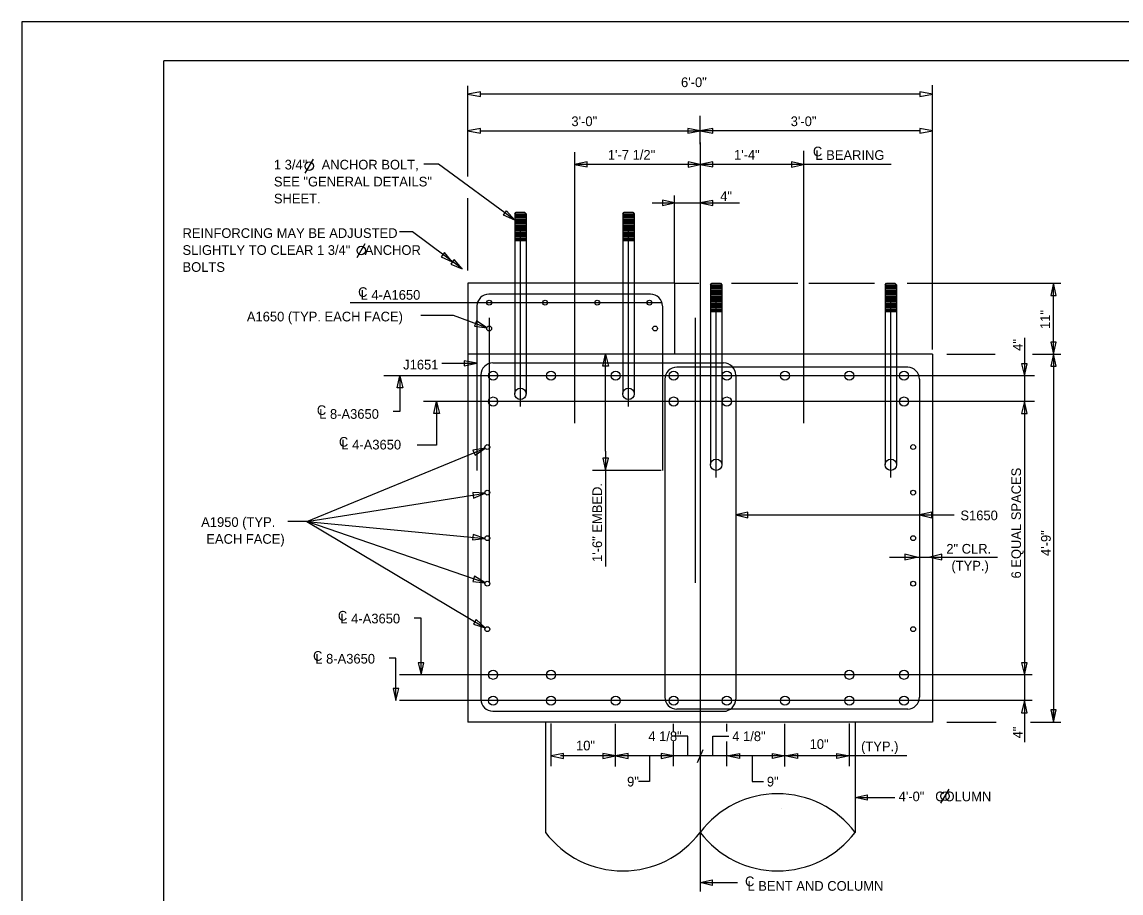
# Model space of a CAD drawing. Extents: x -133.1 to -97, y -1.7 to 20.3.
# Drawn here: x -133.14 to -118.94, y 9.06 to 20.31 of the extents above; entities that cross this region are included whole.
import ezdxf

# ---------------------------------------------------------------- set-up
doc = ezdxf.new("R2010")
doc.units = 0
for name, color, linetype in [('BR_AUTO DIMENSION', 7, 'Continuous'), ('BR_BORDER LINES', 7, 'Continuous'), ('BR_CENTER LINES', 7, 'Continuous'), ('BR_CONCRETE', 7, 'Continuous'), ('BR_REBAR', 7, 'Continuous'), ('BR_STRUCTURAL STEEL', 7, 'Continuous'), ('BR_TEXT', 7, 'Continuous'), ('Level 31', 7, 'Continuous')]:
    doc.layers.add(name, color=color, linetype=linetype)

msp = doc.modelspace()

# ---------------------------------------------------------------- linework, layer by layer
at = {"layer": 'BR_AUTO DIMENSION'}
for p, q in [((-127.38, 18.314), (-127.38, 19.485)), ((-121.38, 16.08), (-121.38, 19.492)), ((-121.546, 19.378), (-127.213, 19.378)), ((-124.38, 18.729), (-124.38, 19.097)), ((-127.213, 18.902), (-124.38, 18.902)), ((-121.546, 18.902), (-124.38, 18.902)), ((-124.38, 18.469), (-126.005, 18.469)), ((-123.046, 18.469), (-124.38, 18.469)), ((-121.914, 18.469), (-123.046, 18.469)), ((-127.38, 17.1), (-127.38, 18.032)), ((-124.713, 16.934), (-124.713, 18.066)), ((-124.38, 18.088), (-124.38, 17.83)), ((-125.001, 17.973), (-123.872, 17.973)), ((-124.713, 16.934), (-124.399, 16.934)), ((-123.978, 16.934), (-123.119, 16.934)), ((-122.978, 16.934), (-122.127, 16.934)), ((-121.706, 16.934), (-119.72, 16.934)), ((-119.817, 16.018), (-119.817, 16.934)), ((-127.566, 16.518), (-127.991, 16.518)), ((-127.136, 16.36), (-127.566, 16.518)), ((-120.192, 16.232), (-120.192, 11.006)), ((-127.717, 15.901), (-127.264, 15.901)), ((-125.602, 14.768), (-125.602, 16.018)), ((-121.193, 16.018), (-120.568, 16.018)), ((-120.087, 16.018), (-119.72, 16.018)), ((-119.817, 16.018), (-119.817, 11.268)), ((-127.785, 15.407), (-127.785, 14.845)), ((-129.46, 13.856), (-127.158, 14.806)), ((-127.785, 14.845), (-128.036, 14.845)), ((-125.602, 14.768), (-125.602, 13.275)), ((-124.885, 14.518), (-125.771, 14.518)), ((-129.46, 13.856), (-127.16, 14.222)), ((-123.921, 13.943), (-121.1, 13.943)), ((-129.46, 13.856), (-127.156, 12.483)), ((-129.46, 13.856), (-127.161, 13.64)), ((-121.933, 13.399), (-120.541, 13.399)), ((-126.307, 10.698), (-126.307, 11.249)), ((-125.473, 10.692), (-125.473, 11.244)), ((-124.724, 11.146), (-124.724, 11.246)), ((-124.036, 11.146), (-124.036, 11.246)), ((-123.286, 10.692), (-123.286, 11.244)), ((-122.453, 10.698), (-122.453, 11.249)), ((-121.193, 11.268), (-120.558, 11.268)), ((-120.114, 11.268), (-119.72, 11.268)), ((-124.542, 11.084), (-124.749, 11.084)), ((-124.542, 10.83), (-124.542, 11.084)), ((-124.217, 10.83), (-124.217, 11.084)), ((-124.217, 11.084), (-124.011, 11.084)), ((-124.724, 10.698), (-124.724, 11.016)), ((-124.036, 10.698), (-124.036, 11.016)), ((-121.709, 10.83), (-126.184, 10.83)), ((-125.034, 10.83), (-125.034, 10.498)), ((-124.417, 10.747), (-124.343, 10.912)), ((-123.707, 10.83), (-123.707, 10.498)), ((-125.034, 10.498), (-125.178, 10.498)), ((-123.707, 10.498), (-123.563, 10.498)), ((-122.38, 10.293), (-121.868, 10.293)), ((-124.38, 9.194), (-123.897, 9.194))]:
    msp.add_line(p, q, dxfattribs=at)
for points in [[(-127.217, 19.409), (-127.38, 19.378), (-127.217, 19.346)], [(-121.542, 19.346), (-121.38, 19.378), (-121.542, 19.409)], [(-127.217, 18.933), (-127.38, 18.902), (-127.217, 18.871)], [(-124.542, 18.871), (-124.38, 18.902), (-124.542, 18.933)], [(-124.217, 18.933), (-124.38, 18.902), (-124.217, 18.871)], [(-121.542, 18.871), (-121.38, 18.902), (-121.542, 18.933)], [(-125.842, 18.501), (-126.005, 18.469), (-125.842, 18.438)], [(-124.536, 18.433), (-124.38, 18.469), (-124.536, 18.505)], [(-124.217, 18.501), (-124.38, 18.469), (-124.217, 18.438)], [(-123.202, 18.433), (-123.046, 18.469), (-123.202, 18.505)], [(-124.869, 17.937), (-124.713, 17.973), (-124.869, 18.009)], [(-124.217, 18.004), (-124.38, 17.973), (-124.217, 17.941)], [(-126.881, 17.872), (-126.776, 17.751), (-126.923, 17.814)], [(-127.728, 17.277), (-127.582, 17.212), (-127.685, 17.334)], [(-127.603, 17.183), (-127.457, 17.119), (-127.56, 17.241)], [(-119.781, 16.778), (-119.817, 16.934), (-119.853, 16.778)], [(-127.295, 16.38), (-127.136, 16.36), (-127.27, 16.448)], [(-119.853, 16.174), (-119.817, 16.018), (-119.781, 16.174)], [(-127.427, 15.87), (-127.264, 15.901), (-127.427, 15.933)], [(-125.638, 15.862), (-125.602, 16.018), (-125.566, 15.862)], [(-119.781, 15.862), (-119.817, 16.018), (-119.853, 15.862)], [(-120.228, 15.896), (-120.192, 15.74), (-120.156, 15.896)], [(-128.295, 15.584), (-128.259, 15.74), (-128.223, 15.584)], [(-127.821, 15.251), (-127.785, 15.407), (-127.749, 15.251)], [(-120.156, 15.251), (-120.192, 15.407), (-120.228, 15.251)], [(-127.289, 14.714), (-127.158, 14.806), (-127.316, 14.78)], [(-125.638, 14.674), (-125.602, 14.518), (-125.566, 14.674)], [(-127.308, 14.161), (-127.16, 14.222), (-127.319, 14.233)], [(-123.765, 13.979), (-123.921, 13.943), (-123.765, 13.907)], [(-121.39, 13.979), (-121.546, 13.943), (-121.39, 13.907)], [(-127.32, 13.619), (-127.161, 13.64), (-127.313, 13.691)], [(-121.738, 13.363), (-121.582, 13.399), (-121.738, 13.435)], [(-121.259, 13.435), (-121.415, 13.399), (-121.259, 13.363)], [(-127.318, 13.082), (-127.159, 13.065), (-127.295, 13.15)], [(-127.309, 12.532), (-127.156, 12.483), (-127.272, 12.594)], [(-128.022, 12.034), (-127.986, 11.878), (-127.95, 12.034)], [(-120.228, 12.034), (-120.192, 11.878), (-120.156, 12.034)], [(-128.347, 11.701), (-128.311, 11.545), (-128.275, 11.701)], [(-120.156, 11.389), (-120.192, 11.545), (-120.228, 11.389)], [(-119.853, 11.424), (-119.817, 11.268), (-119.781, 11.424)], [(-126.144, 10.861), (-126.307, 10.83), (-126.144, 10.799)], [(-125.636, 10.799), (-125.474, 10.83), (-125.636, 10.861)], [(-125.311, 10.861), (-125.474, 10.83), (-125.311, 10.799)], [(-124.886, 10.799), (-124.724, 10.83), (-124.886, 10.861)], [(-123.874, 10.799), (-124.036, 10.83), (-123.874, 10.861)], [(-123.448, 10.861), (-123.286, 10.83), (-123.448, 10.799)], [(-123.123, 10.799), (-123.286, 10.83), (-123.123, 10.861)], [(-122.615, 10.861), (-122.453, 10.83), (-122.615, 10.799)], [(-122.224, 10.257), (-122.38, 10.293), (-122.224, 10.329)], [(-124.224, 9.158), (-124.38, 9.194), (-124.224, 9.23)]]:
    msp.add_lwpolyline(points, close=True, dxfattribs=at)
for points in [[(-126.776, 17.751), (-127.76, 18.471), (-127.951, 18.471)], [(-127.457, 17.119), (-128.098, 17.598), (-128.263, 17.598)], [(-128.259, 15.74), (-128.259, 15.277), (-128.347, 15.277)], [(-127.159, 13.065), (-129.46, 13.856), (-129.708, 13.856)], [(-127.986, 11.878), (-127.986, 12.611), (-128.074, 12.611)], [(-128.311, 11.545), (-128.311, 12.091), (-128.398, 12.091)]]:
    msp.add_lwpolyline(points, dxfattribs=at)
at = {"layer": 'BR_BORDER LINES'}
for p in [(-97.642, 19.809), (-131.308, -1.191)]:
    msp.add_line(p, (-131.308, 19.809), dxfattribs=at)
at = {"layer": 'BR_CENTER LINES'}
for p, q in [((-124.38, 18.751), (-124.38, 9.079)), ((-126.005, 18.628), (-126.005, 15.128)), ((-123.046, 18.647), (-123.046, 15.128)), ((-126.703, 15.341), (-126.703, 17.64)), ((-125.306, 15.341), (-125.306, 17.64)), ((-124.874, 16.684), (-128.903, 16.684)), ((-124.174, 14.424), (-124.174, 16.723)), ((-121.918, 14.424), (-121.918, 16.723)), ((-120.062, 15.74), (-128.468, 15.74)), ((-120.062, 15.407), (-127.956, 15.407)), ((-120.091, 11.878), (-128.266, 11.878)), ((-120.091, 11.545), (-128.266, 11.545))]:
    msp.add_line(p, q, dxfattribs=at)
at = {"layer": 'BR_CONCRETE'}
for p, q in [((-127.38, 16.934), (-127.38, 11.268)), ((-124.713, 16.934), (-127.38, 16.934)), ((-124.713, 16.934), (-124.713, 16.018)), ((-121.38, 16.018), (-127.38, 16.018)), ((-121.38, 16.018), (-121.38, 11.268)), ((-121.38, 11.268), (-127.38, 11.268)), ((-126.38, 11.268), (-126.38, 9.843)), ((-122.38, 11.268), (-122.38, 9.843)), ((-122.38, 11.268), (-122.38, 11.095)), ((-123.336, 10.153), (-123.336, 10.153))]:
    msp.add_line(p, q, dxfattribs=at)
for centre, start, end in [((-123.38, 9.09), 37.0023, 142.9977), ((-125.38, 10.597), 217.0023, 322.9977), ((-123.38, 10.597), 217.0023, 322.9977)]:
    msp.add_arc(centre, 1.252, start, end, dxfattribs=at)
at = {"layer": 'BR_REBAR'}
for p, q in [((-125.022, 16.795), (-127.11, 16.795)), ((-127.264, 16.642), (-127.264, 14.518)), ((-124.868, 16.637), (-124.868, 14.518)), ((-127.059, 15.905), (-124.078, 15.905)), ((-121.7, 15.851), (-124.682, 15.851)), ((-127.213, 15.747), (-127.213, 11.561)), ((-124.838, 15.695), (-124.838, 11.591)), ((-123.921, 15.749), (-123.921, 11.563)), ((-121.546, 15.697), (-121.546, 11.588)), ((-127.059, 11.407), (-124.078, 11.407)), ((-121.7, 11.434), (-124.682, 11.434))]:
    msp.add_line(p, q, dxfattribs=at)
for centre, radius in [((-127.106, 16.684), 0.0313), ((-126.384, 16.684), 0.0313), ((-125.71, 16.684), 0.0313), ((-125.036, 16.684), 0.0313), ((-127.106, 16.351), 0.0313), ((-124.963, 16.351), 0.0313), ((-127.055, 15.74), 0.0588), ((-126.307, 15.74), 0.0588), ((-125.473, 15.74), 0.0588), ((-124.724, 15.74), 0.0588), ((-124.036, 15.74), 0.0588), ((-123.286, 15.74), 0.0588), ((-122.453, 15.74), 0.0588), ((-121.747, 15.74), 0.0588), ((-127.055, 15.407), 0.0588), ((-124.724, 15.407), 0.0588), ((-124.036, 15.407), 0.0588), ((-121.747, 15.407), 0.0588), ((-127.13, 14.819), 0.0313), ((-121.63, 14.819), 0.0313), ((-127.13, 14.231), 0.0313), ((-121.63, 14.231), 0.0313), ((-127.13, 13.643), 0.0313), ((-121.63, 13.643), 0.0313), ((-127.13, 13.055), 0.0313), ((-121.63, 13.055), 0.0313), ((-127.13, 12.467), 0.0313), ((-121.63, 12.467), 0.0313), ((-127.055, 11.878), 0.0588), ((-126.307, 11.878), 0.0588), ((-122.453, 11.878), 0.0588), ((-121.747, 11.878), 0.0588), ((-127.055, 11.545), 0.0588), ((-126.307, 11.545), 0.0588), ((-125.473, 11.545), 0.0588), ((-124.724, 11.545), 0.0588), ((-124.036, 11.545), 0.0588), ((-123.286, 11.545), 0.0588), ((-122.453, 11.545), 0.0588), ((-121.747, 11.545), 0.0588)]:
    msp.add_circle(centre, radius, dxfattribs=at)
for centre, start, end in [((-127.108, 16.639), 91.025, 178.975), ((-125.024, 16.639), 1.025, 88.975), ((-127.057, 15.749), 91.025, 178.975), ((-124.078, 15.749), 360, 90), ((-124.682, 15.695), 90, 180), ((-121.703, 15.695), 1.025, 88.975), ((-127.057, 11.563), 181.025, 268.975), ((-124.682, 11.591), 180, 270), ((-124.078, 11.563), 270, 0), ((-121.703, 11.591), 271.025, 358.975)]:
    msp.add_arc(centre, 0.156, start, end, dxfattribs=at)
at = {"layer": 'BR_STRUCTURAL STEEL'}
for p, q in [((-126.776, 17.833), (-126.758, 17.851)), ((-126.776, 17.833), (-126.63, 17.833)), ((-126.776, 17.833), (-126.776, 16.934)), ((-126.776, 17.815), (-126.63, 17.815)), ((-126.776, 17.797), (-126.63, 17.797)), ((-126.776, 17.778), (-126.63, 17.778)), ((-126.776, 17.76), (-126.63, 17.76)), ((-126.758, 17.851), (-126.648, 17.851)), ((-126.648, 17.851), (-126.63, 17.833)), ((-126.63, 17.833), (-126.63, 16.934)), ((-125.379, 17.833), (-125.361, 17.851)), ((-125.379, 17.833), (-125.234, 17.833)), ((-125.379, 17.833), (-125.379, 16.934)), ((-125.379, 17.815), (-125.234, 17.815)), ((-125.379, 17.797), (-125.234, 17.797)), ((-125.379, 17.778), (-125.234, 17.778)), ((-125.379, 17.76), (-125.234, 17.76)), ((-125.361, 17.851), (-125.252, 17.851)), ((-125.252, 17.851), (-125.234, 17.833)), ((-125.234, 17.833), (-125.234, 16.934)), ((-126.776, 17.742), (-126.63, 17.742)), ((-126.776, 17.724), (-126.63, 17.724)), ((-126.776, 17.705), (-126.63, 17.705)), ((-126.776, 17.687), (-126.63, 17.687)), ((-126.776, 17.669), (-126.63, 17.669)), ((-126.776, 17.651), (-126.63, 17.651)), ((-126.776, 17.632), (-126.63, 17.632)), ((-126.776, 17.614), (-126.63, 17.614)), ((-125.379, 17.742), (-125.234, 17.742)), ((-125.379, 17.724), (-125.234, 17.724)), ((-125.379, 17.705), (-125.234, 17.705)), ((-125.379, 17.687), (-125.234, 17.687)), ((-125.379, 17.669), (-125.234, 17.669)), ((-125.379, 17.651), (-125.234, 17.651)), ((-125.379, 17.632), (-125.234, 17.632)), ((-125.379, 17.614), (-125.234, 17.614)), ((-126.776, 17.596), (-126.63, 17.596)), ((-126.776, 17.578), (-126.63, 17.578)), ((-126.776, 17.56), (-126.63, 17.56)), ((-126.776, 17.541), (-126.63, 17.541)), ((-126.776, 17.523), (-126.63, 17.523)), ((-126.776, 17.505), (-126.63, 17.505)), ((-126.776, 17.487), (-126.63, 17.487)), ((-125.379, 17.596), (-125.234, 17.596)), ((-125.379, 17.578), (-125.234, 17.578)), ((-125.379, 17.56), (-125.234, 17.56)), ((-125.379, 17.541), (-125.234, 17.541)), ((-125.379, 17.523), (-125.234, 17.523)), ((-125.379, 17.505), (-125.234, 17.505)), ((-125.379, 17.487), (-125.234, 17.487)), ((-126.776, 16.934), (-126.776, 15.51)), ((-126.63, 16.934), (-126.63, 15.507)), ((-125.379, 16.934), (-125.379, 15.51)), ((-125.234, 16.934), (-125.234, 15.507)), ((-124.247, 16.916), (-124.229, 16.935)), ((-124.247, 16.916), (-124.102, 16.916)), ((-124.247, 16.916), (-124.247, 16.018)), ((-124.247, 16.898), (-124.102, 16.898)), ((-124.229, 16.935), (-124.12, 16.935)), ((-124.12, 16.935), (-124.102, 16.916)), ((-124.102, 16.916), (-124.102, 16.018)), ((-121.991, 16.916), (-121.973, 16.935)), ((-121.991, 16.916), (-121.846, 16.916)), ((-121.991, 16.916), (-121.991, 16.018)), ((-121.991, 16.898), (-121.846, 16.898)), ((-121.973, 16.935), (-121.864, 16.935)), ((-121.864, 16.935), (-121.846, 16.916)), ((-121.846, 16.916), (-121.846, 16.018)), ((-124.247, 16.88), (-124.102, 16.88)), ((-124.247, 16.862), (-124.102, 16.862)), ((-124.247, 16.843), (-124.102, 16.843)), ((-124.247, 16.825), (-124.102, 16.825)), ((-124.247, 16.807), (-124.102, 16.807)), ((-124.247, 16.789), (-124.102, 16.789)), ((-124.247, 16.77), (-124.102, 16.77)), ((-124.247, 16.752), (-124.102, 16.752)), ((-121.991, 16.88), (-121.846, 16.88)), ((-121.991, 16.862), (-121.846, 16.862)), ((-121.991, 16.843), (-121.846, 16.843)), ((-121.991, 16.825), (-121.846, 16.825)), ((-121.991, 16.807), (-121.846, 16.807)), ((-121.991, 16.789), (-121.846, 16.789)), ((-121.991, 16.77), (-121.846, 16.77)), ((-121.991, 16.752), (-121.846, 16.752)), ((-124.247, 16.734), (-124.102, 16.734)), ((-124.247, 16.716), (-124.102, 16.716)), ((-124.247, 16.698), (-124.102, 16.698)), ((-124.247, 16.679), (-124.102, 16.679)), ((-124.247, 16.661), (-124.102, 16.661)), ((-124.247, 16.643), (-124.102, 16.643)), ((-124.247, 16.625), (-124.102, 16.625)), ((-121.991, 16.734), (-121.846, 16.734)), ((-121.991, 16.716), (-121.846, 16.716)), ((-121.991, 16.698), (-121.846, 16.698)), ((-121.991, 16.679), (-121.846, 16.679)), ((-121.991, 16.661), (-121.846, 16.661)), ((-121.991, 16.643), (-121.846, 16.643)), ((-121.991, 16.625), (-121.846, 16.625)), ((-124.247, 16.606), (-124.102, 16.606)), ((-124.247, 16.588), (-124.102, 16.588)), ((-124.247, 16.57), (-124.102, 16.57)), ((-121.991, 16.606), (-121.846, 16.606)), ((-121.991, 16.588), (-121.846, 16.588)), ((-121.991, 16.57), (-121.846, 16.57)), ((-124.247, 16.018), (-124.247, 14.593)), ((-124.101, 16.018), (-124.101, 14.591)), ((-121.991, 16.018), (-121.991, 14.593)), ((-121.846, 16.018), (-121.845, 14.591))]:
    msp.add_line(p, q, dxfattribs=at)
for centre in [(-126.703, 15.507), (-125.306, 15.507), (-124.174, 14.591), (-121.918, 14.591)]:
    msp.add_circle(centre, 0.0729, dxfattribs=at)
at = {"layer": 'BR_TEXT'}
for p, q in [((-129.482, 18.356), (-129.377, 18.537)), ((-128.811, 17.267), (-128.706, 17.448)), ((-119.817, 11.268), (-119.817, 11.415)), ((-121.27, 10.22), (-121.165, 10.402))]:
    msp.add_line(p, q, dxfattribs=at)
for centre in [(-129.43, 18.447), (-128.758, 17.358), (-121.218, 10.311)]:
    msp.add_circle(centre, 0.055, dxfattribs=at)
at = {"layer": 'Level 31'}
for p, q in [((-127.106, 16.49), (-127.106, 13.067)), ((-124.444, 16.49), (-124.444, 13.067))]:
    msp.add_line(p, q, dxfattribs=at)
msp.add_lwpolyline([(-133.141, -1.691), (-97.141, -1.691), (-97.141, 20.309), (-133.141, 20.309)], close=True, dxfattribs=at)

# ---------------------------------------------------------------- texts
at = {"layer": 'BR_AUTO DIMENSION'}
for s, p in [('6\'-0"', (-124.628, 19.468)), ('3\'-0"', (-126.044, 18.964)), ('3\'-0"', (-123.211, 18.964))]:
    msp.add_text(s, height=0.125, dxfattribs=at).set_placement(p)
at = {"layer": 'BR_TEXT'}
for s, p in [('1\'-7 1/2"', (-125.573, 18.531)), ('1\'-4"', (-123.944, 18.531)), ('C', (-122.924, 18.574)), ('L BEARING', (-122.892, 18.528)), ('4"', (-124.121, 17.997)), ('C', (-128.799, 16.758)), ('L 4-A1650', (-128.767, 16.722)), ('A1650 (TYP. EACH FACE)', (-130.236, 16.442)), ('J1651', (-128.217, 15.821)), ('C', (-129.332, 15.233)), ('L 8-A3650', (-129.302, 15.184)), ('C', (-129.047, 14.824)), ('L 4-A3650', (-129.015, 14.788)), ('A1950 (TYP.', (-130.826, 13.788)), ('S1650', (-121.019, 13.874)), ('EACH FACE)', (-130.76, 13.57)), ('2" CLR.', (-121.201, 13.443)), ('(TYP.)', (-121.135, 13.225)), ('C', (-129.06, 12.578)), ('L 4-A3650', (-129.028, 12.542)), ('C', (-129.381, 12.059)), ('L 8-A3650', (-129.352, 12.023)), ('4 1/8"', (-125.05, 11.022)), ('4 1/8"', (-123.966, 11.022))]:
    msp.add_text(s, height=0.125, dxfattribs=at).set_placement(p)
for s, rotation, p in [('1 3/4"    ANCHOR BOLT, ', 360, (-129.887, 18.404)), ('SEE "GENERAL DETAILS"', 360, (-129.887, 18.185)), ('SHEET.', 360, (-129.887, 17.966)), ('REINFORCING MAY BE ADJUSTED', 360, (-131.067, 17.52)), ('SLIGHTLY TO CLEAR 1 3/4"    ANCHOR', 360, (-131.067, 17.301)), ('BOLTS', 360, (-131.067, 17.082)), ('11"', 90, (-119.862, 16.344)), ('4"', 90, (-120.215, 16.061)), ('6 EQUAL SPACES', 90, (-120.236, 13.122)), ('1\'-6" EMBED.', 90, (-125.648, 13.335)), ('4\'-9"', 90, (-119.852, 13.412)), ('4"', 90, (-120.215, 11.057)), ('10"', 360, (-125.984, 10.902)), ('10"', 360, (-122.967, 10.921)), ('(TYP.)', 360, (-122.302, 10.891)), ('9"', 360, (-125.325, 10.436)), ('9"', 360, (-123.519, 10.436)), ('4\'-0"   COLUMN', 360, (-121.817, 10.245)), ('C', 360, (-123.801, 9.148)), ('L BENT AND COLUMN', 360, (-123.77, 9.089))]:
    msp.add_text(s, height=0.125, rotation=rotation, dxfattribs=at).set_placement(p)

doc.saveas('drawing.dxf')
